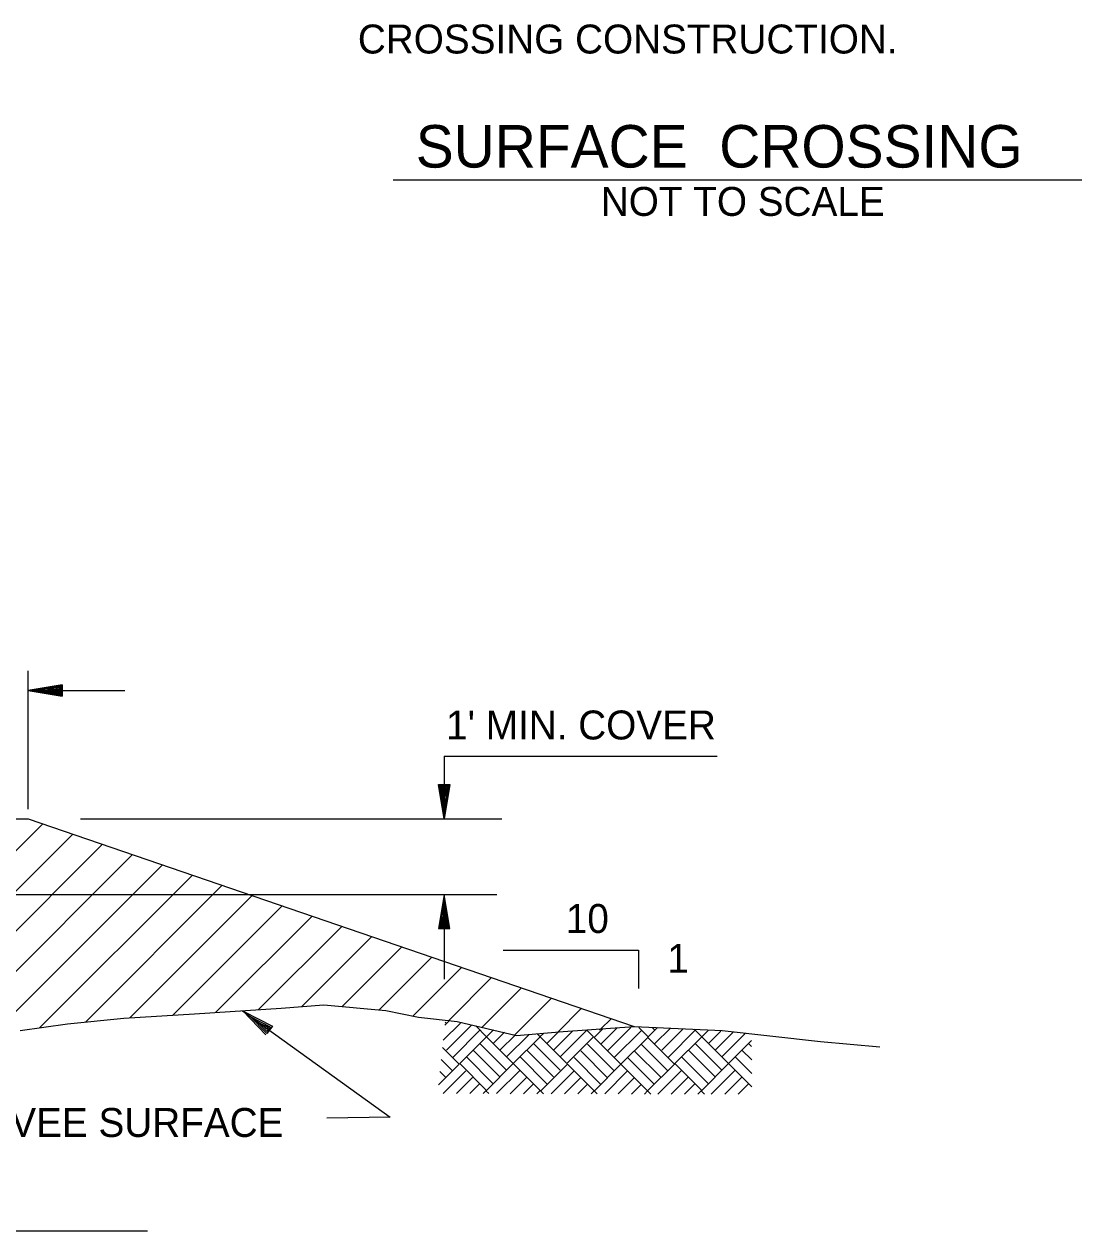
# Model space of a CAD drawing. Extents: x 2127959 to 2137375, y 2146193 to 2153470.
# Drawn here: x 2130299 to 2131502, y 2148467 to 2149840 of the extents above; entities that cross this region are included whole.
import ezdxf

# ---------------------------------------------------------------- set-up
doc = ezdxf.new("R2010")
doc.units = 0
for name, color, linetype in [('Level 1', 7, 'Continuous'), ('Level 3', 7, 'Continuous'), ('Level 5', 7, 'Continuous'), ('Level 50', 7, 'Continuous'), ('Level 63', 7, 'Continuous')]:
    doc.layers.add(name, color=color, linetype=linetype)

msp = doc.modelspace()

# ---------------------------------------------------------------- linework, layer by layer
at = {"layer": 'Level 1'}
for p, q in [((2130001.469, 2148936.091), (2130303.174, 2148936.091)), ((2130303.174, 2148936.091), (2130992.774, 2148699.457)), ((2130303.174, 2148936.091), (2130992.774, 2148699.457)), ((2130303.174, 2148936.091), (2130992.774, 2148699.457)), ((2130715.174, 2148596.311), (2130643.163, 2148595.083))]:
    msp.add_line(p, q, dxfattribs=at)
at = {"layer": 'Level 3'}
for p, q in [((2130303.174, 2148946.778), (2130303.174, 2149104.509)), ((2130341.925, 2149088.339), (2130303.174, 2149081.872)), ((2130341.121, 2149087.562), (2130309.724, 2149082.318)), ((2130340.449, 2149086.75), (2130315.959, 2149082.822)), ((2130339.515, 2149085.789), (2130325.214, 2149083.647)), ((2130339.587, 2149083.441), (2130339.515, 2149085.789)), ((2130340.509, 2149082.683), (2130340.449, 2149086.75)), ((2130341.182, 2149082.787), (2130341.121, 2149087.562)), ((2130341.925, 2149088.339), (2130341.925, 2149075.426)), ((2130303.174, 2149081.872), (2130413.271, 2149081.872)), ((2130303.174, 2149081.872), (2130341.925, 2149081.872)), ((2130303.174, 2149081.872), (2130341.925, 2149075.426)), ((2130309.724, 2149082.318), (2130340.509, 2149082.683)), ((2130341.295, 2149076.285), (2130309.822, 2149081.27)), ((2130309.822, 2149081.27), (2130340.449, 2149081.27)), ((2130315.959, 2149082.822), (2130339.587, 2149083.441)), ((2130340.547, 2149077.081), (2130316.11, 2149080.786)), ((2130316.11, 2149080.786), (2130339.684, 2149080.544)), ((2130325.214, 2149083.647), (2130338.801, 2149083.872)), ((2130339.662, 2149077.994), (2130325.4, 2149080.047)), ((2130325.4, 2149080.047), (2130338.897, 2149079.821)), ((2130339.072, 2149078.686), (2130334.749, 2149079.268)), ((2130338.859, 2149085.046), (2130334.761, 2149084.425)), ((2130338.801, 2149083.872), (2130338.859, 2149085.046)), ((2130338.897, 2149079.821), (2130339.072, 2149078.686)), ((2130339.684, 2149080.544), (2130339.662, 2149077.994)), ((2130340.449, 2149081.27), (2130340.547, 2149077.081)), ((2130341.231, 2149081.249), (2130341.295, 2149076.285)), ((2130776.616, 2149007.311), (2130776.616, 2148936.091)), ((2130776.616, 2149007.311), (2130776.616, 2148936.091)), ((2130776.616, 2149007.311), (2130776.616, 2148936.091)), ((2130776.616, 2149007.311), (2131087.086, 2149007.311)), ((2130770.152, 2148974.843), (2130783.061, 2148974.843)), ((2130776.616, 2148936.091), (2130770.152, 2148974.843)), ((2130776.014, 2148974.206), (2130771.032, 2148974.296)), ((2130771.032, 2148974.296), (2130775.993, 2148944.086)), ((2130775.993, 2148973.45), (2130771.997, 2148973.567)), ((2130771.997, 2148973.567), (2130775.374, 2148951.539)), ((2130775.238, 2148972.607), (2130772.946, 2148972.691)), ((2130772.946, 2148972.691), (2130774.53, 2148961.588)), ((2130774.53, 2148961.588), (2130774.337, 2148971.949)), ((2130775.374, 2148951.539), (2130775.238, 2148972.607)), ((2130775.993, 2148944.086), (2130775.993, 2148973.45)), ((2130776.616, 2148936.091), (2130776.616, 2148974.843)), ((2130783.061, 2148974.843), (2130776.616, 2148936.091)), ((2130782.22, 2148974.173), (2130777.2, 2148944.005)), ((2130777.2, 2148944.005), (2130777.358, 2148973.45)), ((2130777.341, 2148974.255), (2130782.22, 2148974.173)), ((2130777.358, 2148973.45), (2130781.304, 2148973.308)), ((2130781.304, 2148973.308), (2130777.822, 2148951.381)), ((2130777.822, 2148951.381), (2130778.133, 2148972.619)), ((2130778.133, 2148972.619), (2130780.39, 2148972.619)), ((2130780.39, 2148972.619), (2130778.668, 2148961.605)), ((2130778.668, 2148961.605), (2130778.824, 2148971.967)), ((2130362.888, 2148936.091), (2130842.217, 2148936.091)), ((2130362.888, 2148936.091), (2130842.217, 2148936.091)), ((2130362.888, 2148936.091), (2130842.217, 2148936.091)), ((2130190.765, 2148849.885), (2130836.581, 2148849.885)), ((2130190.765, 2148849.885), (2130836.581, 2148849.885)), ((2130190.765, 2148849.885), (2130836.581, 2148849.885)), ((2130776.616, 2148849.885), (2130770.152, 2148811.136)), ((2130771.032, 2148811.683), (2130775.993, 2148841.892)), ((2130775.993, 2148841.892), (2130775.993, 2148812.52)), ((2130776.616, 2148849.885), (2130776.616, 2148753.352)), ((2130776.616, 2148849.885), (2130776.616, 2148811.136)), ((2130783.061, 2148811.136), (2130776.616, 2148849.885)), ((2130782.22, 2148811.799), (2130777.2, 2148841.98)), ((2130777.2, 2148841.98), (2130777.358, 2148812.529)), ((2130771.997, 2148812.409), (2130775.374, 2148834.441)), ((2130772.946, 2148813.285), (2130774.53, 2148824.383)), ((2130774.53, 2148824.383), (2130774.337, 2148814.028)), ((2130775.374, 2148834.441), (2130775.238, 2148813.373)), ((2130781.304, 2148812.66), (2130777.822, 2148834.588)), ((2130777.822, 2148834.588), (2130778.133, 2148813.361)), ((2130780.39, 2148813.354), (2130778.668, 2148824.366)), ((2130778.668, 2148824.366), (2130778.824, 2148814.014)), ((2130770.152, 2148811.136), (2130783.061, 2148811.136)), ((2130776.014, 2148811.776), (2130771.032, 2148811.683)), ((2130775.993, 2148812.52), (2130771.997, 2148812.409)), ((2130775.238, 2148813.373), (2130772.946, 2148813.285)), ((2130777.341, 2148811.721), (2130782.22, 2148811.799)), ((2130777.358, 2148812.529), (2130781.304, 2148812.66)), ((2130778.133, 2148813.361), (2130780.39, 2148813.354)), ((2130843.629, 2148786.364), (2130997.757, 2148786.364)), ((2130997.757, 2148786.364), (2130997.757, 2148742.633))]:
    msp.add_line(p, q, dxfattribs=at)
msp.add_lwpolyline([(2130547.199, 2148717.545), (2130715.174, 2148596.311)], dxfattribs=at)
at = {"layer": 'Level 5'}
for p, q in [((2130207.28, 2148817.725), (2130319.902, 2148930.349)), ((2130166.072, 2148685.086), (2130387.975, 2148906.991)), ((2130216.843, 2148781.571), (2130353.941, 2148918.659)), ((2130225.007, 2148698.303), (2130422.013, 2148895.308)), ((2130270, 2148697.582), (2130456.049, 2148883.631)), ((2130316.307, 2148698.177), (2130490.081, 2148871.951)), ((2130368.67, 2148704.823), (2130524.116, 2148860.274)), ((2130419.192, 2148709.632), (2130558.148, 2148848.595)), ((2130467.776, 2148712.499), (2130592.198, 2148836.916)), ((2130516.527, 2148715.532), (2130626.229, 2148825.235)), ((2130565.44, 2148718.743), (2130660.263, 2148813.556)), ((2130614.611, 2148722.183), (2130694.293, 2148801.878)), ((2130660.386, 2148722.239), (2130728.346, 2148790.202)), ((2130702.43, 2148718.576), (2130762.375, 2148778.519)), ((2130740.931, 2148711.365), (2130796.408, 2148766.843)), ((2130781.702, 2148706.427), (2130830.439, 2148755.161)), ((2130819.665, 2148698.668), (2130864.474, 2148743.483)), ((2130856.577, 2148689.861), (2130898.523, 2148731.803)), ((2130492.343, 2148713.945), (2130591.027, 2148720.422)), ((2130591.027, 2148720.422), (2130639.577, 2148724.05)), ((2130639.577, 2148724.05), (2130710.243, 2148717.894)), ((2130710.243, 2148717.894), (2130747.345, 2148709.999)), ((2130905.657, 2148693.226), (2130932.555, 2148720.124)), ((2130294.175, 2148694.997), (2130348.058, 2148702.737)), ((2130348.058, 2148702.737), (2130412.007, 2148709.209)), ((2130412.007, 2148709.209), (2130492.343, 2148713.945)), ((2130747.345, 2148709.999), (2130791.357, 2148705.419)), ((2130775.495, 2148684.044), (2130794.978, 2148703.523)), ((2130782.202, 2148705.997), (2130777.358, 2148701.164)), ((2130779.082, 2148702.931), (2130777.704, 2148704.309)), ((2130779.138, 2148672.455), (2130807.735, 2148701.051)), ((2130791.357, 2148705.419), (2130858.852, 2148689.313)), ((2130954.932, 2148696.784), (2130966.586, 2148708.448)), ((2130817.252, 2148695.294), (2130786.739, 2148664.793)), ((2130794.237, 2148657.338), (2130824.717, 2148687.822)), ((2130812.39, 2148700.15), (2130824.84, 2148687.691)), ((2130824.717, 2148687.816), (2130832.665, 2148695.769)), ((2130855.181, 2148657.338), (2130824.717, 2148687.816)), ((2130832.32, 2148680.217), (2130845.079, 2148692.978)), ((2130857.559, 2148690.177), (2130839.959, 2148672.578)), ((2130873.094, 2148690.5), (2130847.56, 2148664.962)), ((2130855.197, 2148657.338), (2130885.664, 2148687.816)), ((2130858.852, 2148689.313), (2130911.745, 2148693.735)), ((2130885.664, 2148687.816), (2130882.214, 2148691.26)), ((2130889.748, 2148691.89), (2130885.541, 2148687.684)), ((2130885.664, 2148687.816), (2130916.141, 2148657.338)), ((2130893.299, 2148680.187), (2130906.385, 2148693.274)), ((2130900.898, 2148672.571), (2130922.846, 2148694.519)), ((2130938.899, 2148695.283), (2130908.539, 2148664.934)), ((2130911.745, 2148693.735), (2130992.774, 2148699.457)), ((2130946.502, 2148687.684), (2130916.141, 2148657.335)), ((2130946.537, 2148687.684), (2130938.59, 2148695.634)), ((2130956.999, 2148696.931), (2130947.157, 2148687.083)), ((2130977.637, 2148656.559), (2130947.157, 2148687.036)), ((2130954.137, 2148695.283), (2130952.794, 2148696.633)), ((2130954.762, 2148679.434), (2130973.413, 2148698.088)), ((2130962.397, 2148671.847), (2130988.827, 2148698.283)), ((2131000.502, 2148694.685), (2130970.001, 2148664.184)), ((2131008.101, 2148687.083), (2130977.637, 2148656.607)), ((2130992.774, 2148699.457), (2131092.753, 2148695.155)), ((2130998.101, 2148698.312), (2131008.722, 2148687.702)), ((2131008.101, 2148687.036), (2131038.465, 2148656.686)), ((2131019.378, 2148698.314), (2131008.775, 2148687.702)), ((2131016.36, 2148695.305), (2131013.307, 2148698.357)), ((2131016.36, 2148680.052), (2131033.997, 2148697.683)), ((2131023.998, 2148672.464), (2131048.598, 2148697.058)), ((2131062.114, 2148695.305), (2131031.617, 2148664.801)), ((2131039.117, 2148657.347), (2131069.598, 2148687.83)), ((2131060.889, 2148696.524), (2131069.716, 2148687.702)), ((2131069.58, 2148687.826), (2131077.253, 2148695.487)), ((2131100.06, 2148657.347), (2131069.58, 2148687.826)), ((2131077.183, 2148680.224), (2131091.267, 2148694.3)), ((2131105.337, 2148693.107), (2131084.822, 2148672.585)), ((2131119.386, 2148691.919), (2131092.442, 2148664.976)), ((2131092.753, 2148695.155), (2131204.844, 2148682.367)), ((2130774.581, 2148675.68), (2130793.58, 2148656.674)), ((2130817.063, 2148680.217), (2130847.56, 2148649.714)), ((2130878.057, 2148680.217), (2130908.573, 2148649.714)), ((2130939.503, 2148679.434), (2130970.001, 2148648.933)), ((2131000.502, 2148679.434), (2131030.856, 2148649.082)), ((2131061.945, 2148680.224), (2131092.442, 2148649.725)), ((2131100.06, 2148657.347), (2131126.198, 2148683.484)), ((2131122.938, 2148680.224), (2131126.249, 2148676.91)), ((2131204.844, 2148682.367), (2131272.357, 2148676.524)), ((2130773.082, 2148661.977), (2130785.978, 2148649.077)), ((2130832.32, 2148634.462), (2130801.804, 2148664.962)), ((2130809.478, 2148672.578), (2130839.959, 2148642.101)), ((2130893.314, 2148634.462), (2130862.818, 2148664.962)), ((2130900.898, 2148642.101), (2130870.42, 2148672.578)), ((2130954.762, 2148633.681), (2130924.26, 2148664.184)), ((2130931.919, 2148671.793), (2130962.397, 2148641.319)), ((2131015.601, 2148633.835), (2130985.259, 2148664.184)), ((2131023.22, 2148641.446), (2130992.859, 2148671.793)), ((2131077.183, 2148634.474), (2131046.686, 2148664.976)), ((2131054.338, 2148672.585), (2131084.822, 2148642.111)), ((2131126.49, 2148646.164), (2131107.679, 2148664.975)), ((2131126.369, 2148661.515), (2131115.299, 2148672.585)), ((2130769.91, 2148633.005), (2130793.58, 2148656.671)), ((2130778.341, 2148641.439), (2130771.583, 2148648.205)), ((2130775.408, 2148623.293), (2130801.203, 2148649.095)), ((2130824.717, 2148626.864), (2130794.237, 2148657.338)), ((2130824.717, 2148626.814), (2130855.197, 2148657.293)), ((2130836.235, 2148623.137), (2130862.818, 2148649.714)), ((2130855.181, 2148657.338), (2130885.664, 2148626.864)), ((2130886.317, 2148626.215), (2130916.796, 2148656.692)), ((2130898.282, 2148622.97), (2130924.436, 2148649.112)), ((2130947.276, 2148626.215), (2130916.796, 2148656.692)), ((2130916.796, 2148656.692), (2130947.276, 2148626.215)), ((2130977.637, 2148656.559), (2130947.157, 2148626.083)), ((2130977.637, 2148656.559), (2130947.157, 2148626.083)), ((2130977.637, 2148656.559), (2130947.157, 2148626.083)), ((2130959.138, 2148622.813), (2130985.259, 2148648.933)), ((2130959.138, 2148622.813), (2130985.259, 2148648.933)), ((2130959.138, 2148622.813), (2130985.259, 2148648.933)), ((2130977.637, 2148656.559), (2131008.101, 2148626.083)), ((2131007.98, 2148626.203), (2131038.444, 2148656.681)), ((2131007.98, 2148626.203), (2131038.444, 2148656.681)), ((2131007.98, 2148626.203), (2131038.444, 2148656.681)), ((2131019.617, 2148622.644), (2131046.079, 2148649.106)), ((2131019.617, 2148622.644), (2131046.079, 2148649.106)), ((2131019.617, 2148622.644), (2131046.079, 2148649.106)), ((2131069.58, 2148626.872), (2131039.117, 2148657.347)), ((2131069.58, 2148626.822), (2131100.06, 2148657.297)), ((2131080.457, 2148622.486), (2131107.679, 2148649.725)), ((2131100.06, 2148657.347), (2131126.626, 2148630.789)), ((2130808.82, 2148641.435), (2130790.634, 2148623.255)), ((2130816.459, 2148633.843), (2130805.823, 2148623.215)), ((2130870.42, 2148642.054), (2130851.472, 2148623.092)), ((2130878.057, 2148634.462), (2130866.663, 2148623.051)), ((2130932.037, 2148641.453), (2130913.521, 2148622.929)), ((2130939.678, 2148633.863), (2130928.708, 2148622.891)), ((2130974.327, 2148622.767), (2130992.859, 2148641.319)), ((2131000.502, 2148633.681), (2130989.551, 2148622.727)), ((2131000.502, 2148633.681), (2130989.551, 2148622.727)), ((2131000.502, 2148633.681), (2130989.551, 2148622.727)), ((2131053.684, 2148641.441), (2131034.859, 2148622.608)), ((2131053.684, 2148641.441), (2131034.859, 2148622.608)), ((2131053.684, 2148641.441), (2131034.859, 2148622.608)), ((2131061.319, 2148633.856), (2131050.047, 2148622.568)), ((2131061.319, 2148633.856), (2131050.047, 2148622.568)), ((2131061.319, 2148633.856), (2131050.047, 2148622.568)), ((2131115.299, 2148642.061), (2131095.681, 2148622.444)), ((2131122.938, 2148634.474), (2131110.867, 2148622.408)), ((2130821.027, 2148623.173), (2130824.062, 2148626.194)), ((2130827.149, 2148623.159), (2130824.098, 2148626.194)), ((2130881.869, 2148623.013), (2130885.664, 2148626.814)), ((2130886.284, 2148626.215), (2130889.488, 2148622.99)), ((2130943.916, 2148622.849), (2130947.276, 2148626.215)), ((2130947.276, 2148626.215), (2130950.658, 2148622.83)), ((2131004.463, 2148622.688), (2131007.98, 2148626.203)), ((2131011.516, 2148622.669), (2131007.98, 2148626.203)), ((2131011.516, 2148622.669), (2131007.98, 2148626.203)), ((2131011.516, 2148622.669), (2131007.98, 2148626.203)), ((2131065.252, 2148622.528), (2131068.924, 2148626.203)), ((2131065.252, 2148622.528), (2131068.924, 2148626.203)), ((2131065.252, 2148622.528), (2131068.924, 2148626.203)), ((2131072.666, 2148622.507), (2131068.975, 2148626.203)), ((2131072.666, 2148622.507), (2131068.975, 2148626.203)), ((2131072.666, 2148622.507), (2131068.975, 2148626.203))]:
    msp.add_line(p, q, dxfattribs=at)
at = {"layer": 'Level 50'}
for p, q in [((2130547.662, 2148716.981), (2130547.662, 2148716.981)), ((2130555.933, 2148710.874), (2130555.933, 2148710.874))]:
    msp.add_line(p, q, dxfattribs=at)
msp.add_lwpolyline([(2130573.782, 2148690.098), (2130547.662, 2148716.981), (2130581.052, 2148699.977), (2130574.842, 2148691.542), (2130555.933, 2148710.874), (2130578.601, 2148699.327), (2130574.619, 2148693.902), (2130563.887, 2148705.009), (2130576.154, 2148698.671), (2130574.52, 2148696.444), (2130572.167, 2148698.905)], dxfattribs=at)
at = {"layer": 'Level 63'}
for p, q in [((2130718.402, 2149663.321), (2131502.003, 2149663.321)), ((2129803.161, 2148466.947), (2130438.856, 2148466.947))]:
    msp.add_line(p, q, dxfattribs=at)

# ---------------------------------------------------------------- texts
at = {"layer": 'Level 1'}
for s, p in [('CROSSING CONSTRUCTION.', (2130678.304, 2149807.041)), ('NOT TO SCALE', (2130954.726, 2149622.214)), ("1' MIN. COVER", (2130778.72, 2149026.274)), ('10', (2130914.918, 2148805.999)), ('1', (2131030.374, 2148760.685)), ('LEVEE SURFACE', (2130229.033, 2148573.84))]:
    msp.add_text(s, height=32.931, dxfattribs=at).set_placement(p)
at = {"layer": 'Level 63'}
msp.add_text('SURFACE  CROSSING', height=48.4, dxfattribs=at).set_placement((2130744.222, 2149677.193))

doc.saveas('drawing.dxf')
